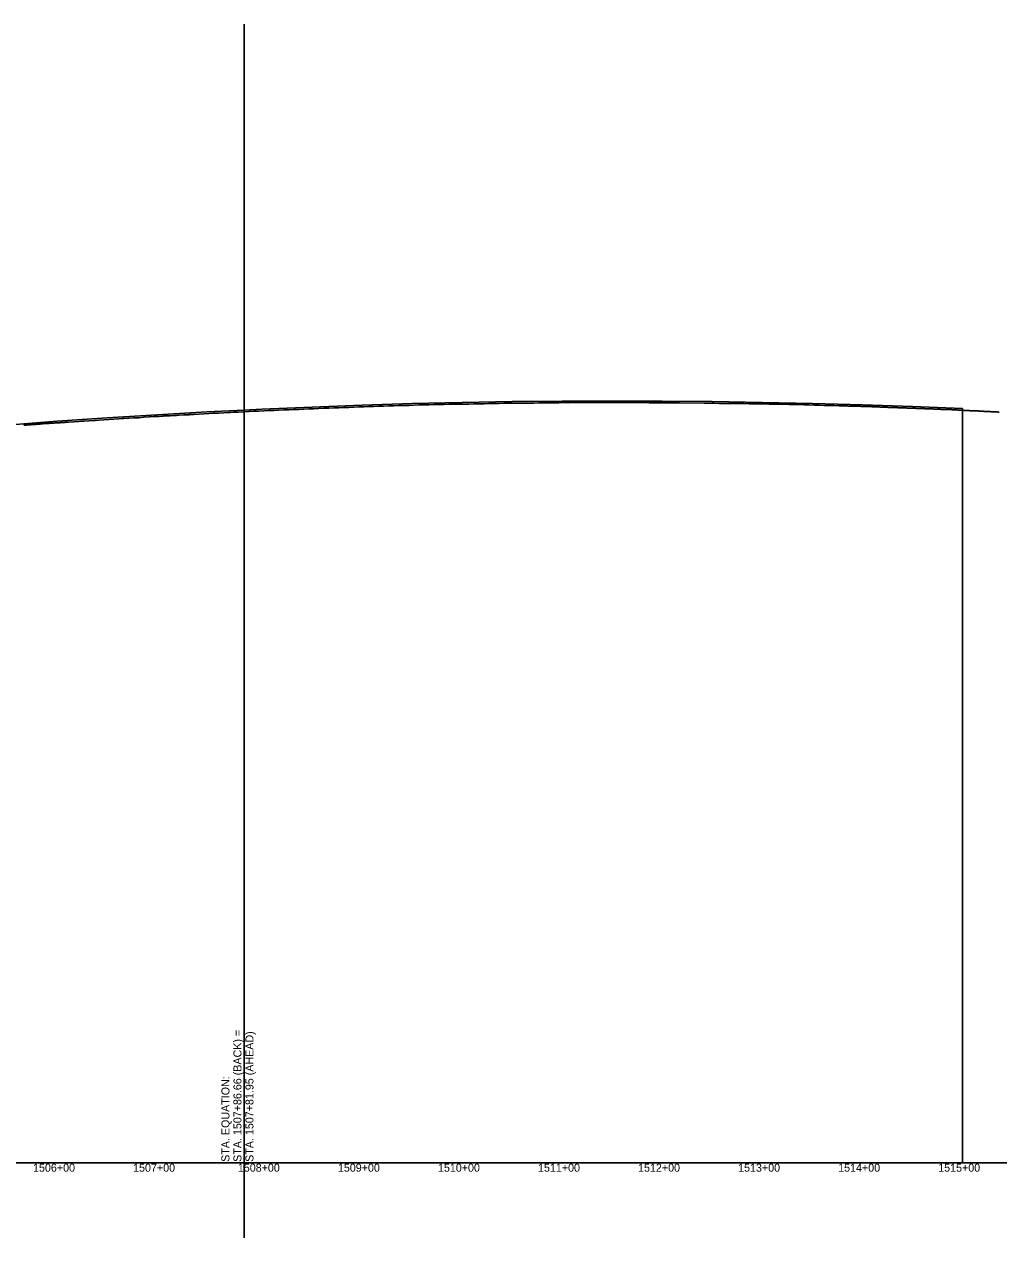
# Model space of a CAD drawing. Extents: x -3793 to 50787, y -1075 to 6138.
# Drawn here: x 38006 to 38979, y -1075 to 138 of the extents above; entities that cross this region are included whole.
import ezdxf

# ---------------------------------------------------------------- set-up
doc = ezdxf.new("R2010")
doc.units = 0
for name, color, linetype in [('RD_DDB_Profile_EX', 7, 'Continuous'), ('RD_DDB_Profile_PR', 7, 'Continuous'), ('RD_DDB_StaTX', 7, 'Continuous'), ('RD_GPK_Profile_Cell', 7, 'Continuous'), ('RD_Sketch10', 7, 'Continuous')]:
    doc.layers.add(name, color=color, linetype=linetype)

msp = doc.modelspace()

# ---------------------------------------------------------------- linework, layer by layer
at = {"layer": 'RD_DDB_Profile_EX'}
for points in [[(38225.12583, -249.34735), (38229.923127, -249.107085), (38234.921278, -248.85725), (38239.91943, -248.60742), (38244.914277, -248.307705), (38249.921926, -248.107355), (38254.916721, -247.95605), (38259.914874, -247.656985), (38264.919173, -247.45596), (38269.914027, -247.255755), (38274.91218, -247.105605), (38279.916482, -246.904965), (38284.914634, -246.60574), (38289.909419, -246.50461), (38294.904246, -246.304085), (38299.911928, -246.054385), (38304.906705, -245.85404), (38309.90486, -245.65423), (38314.909207, -245.45351), (38319.907362, -245.303505), (38324.905517, -245.153685), (38329.907033, -244.905105), (38334.90522, -244.70477), (38339.906728, -244.456305), (38344.914373, -244.306045), (38349.915949, -244.157005), (38354.914076, -244.00681), (38359.915634, -243.75899), (38364.913756, -243.65919), (38369.911877, -243.558495), (38374.912871, -243.407015), (38379.907641, -243.156765), (38384.911987, -243.056315), (38389.906757, -242.9554), (38394.901526, -242.75478), (38399.902501, -242.55338), (38404.897278, -242.452735), (38409.901607, -242.30204), (38414.896376, -242.201235), (38419.900723, -242.10048), (38423.783513, -242.022265), (38424.895965, -242.0001), (38429.892311, -241.85117), (38434.899805, -241.801125), (38439.89729, -241.75091), (38444.894194, -241.65144), (38449.901704, -241.651395), (38454.899173, -241.50134), (38459.896101, -241.401715), (38464.893566, -241.25168), (38469.901076, -241.151635), (38474.898544, -241.101375), (38479.895454, -240.95184), (38484.892924, -240.85181), (38489.899879, -240.802255), (38494.896791, -240.752715), (38499.903704, -240.753275), (38504.900612, -240.654), (38509.89752, -240.70419), (38514.904408, -240.654745), (38519.901386, -240.5552), (38524.908257, -240.505755), (38529.905163, -240.4071), (38534.902069, -240.35714), (38539.908914, -240.307215), (38544.905362, -240.20886), (38549.912187, -240.259445), (38554.90977, -240.208685), (38559.906657, -240.208505), (38564.914179, -240.20653), (38589.48124, -240.20871), (38590.094524, -240.20887), (38614.922181, -240.22192), (38619.925883, -240.17011), (38624.930332, -240.22002), (38629.928395, -240.32082), (38634.790286, -240.354835), (38635.484839, -240.35691), (38659.827095, -240.528185), (38660.275519, -240.529525), (38684.9043, -240.704345), (38689.901765, -240.754615), (38694.899231, -240.85412), (38699.897327, -240.903845), (38704.894792, -240.953725), (38709.902239, -240.953995), (38714.900324, -241.10304), (38719.89779, -241.102915), (38724.895818, -241.20226), (38729.893286, -241.252135), (38734.891337, -241.301605), (38739.888804, -241.45124), (38744.896853, -241.550725), (38749.894322, -241.650605), (38755.190084, -241.658935), (38759.890462, -241.800175), (38761.390288, -241.815015), (38764.886732, -241.85028), (38769.893123, -241.95129), (38774.88948, -242.00239), (38779.896393, -242.103135)], [(38779.896393, -242.103135), (38784.892742, -242.303595), (38789.899063, -242.454585), (38794.895973, -242.605385), (38799.902257, -242.75695), (38804.898709, -242.906855), (38809.905545, -243.057315), (38814.901891, -243.10957), (38820.037785, -243.260785), (38821.028694, -243.3097), (38822.023276, -243.359295), (38823.027495, -243.408275), (38824.020655, -243.45771), (38825.024876, -243.45811), (38826.019448, -243.55773), (38827.023804, -243.55743), (38828.026599, -243.557645), (38829.021183, -243.60726), (38830.025522, -243.60755), (38831.01998, -243.65713), (38832.022901, -243.65793), (38833.027258, -243.65758), (38834.021701, -243.70663), (38835.026059, -243.75582), (38836.019081, -243.756445), (38837.023439, -243.75612), (38838.027783, -243.805355), (38839.022243, -243.85497), (38840.025163, -243.855185), (38841.019691, -243.855205), (38842.023971, -243.954125), (38843.017069, -243.95463), (38844.021351, -244.00433), (38845.0257, -244.0537), (38846.020222, -244.05365), (38847.023081, -244.103865), (38848.0176, -244.05406), (38849.021947, -244.053975), (38850.026255, -244.15312), (38851.019326, -244.20351), (38852.023681, -244.20316), (38853.018132, -244.25271), (38854.022488, -244.30253), (38855.025373, -244.252985), (38856.019867, -244.252625), (38857.024219, -244.302325), (38858.018678, -244.40165), (38859.021599, -244.501725), (38860.016073, -244.55124), (38861.020412, -244.600865), (38862.024769, -244.60052), (38863.017792, -244.650695), (38864.022149, -244.750255), (38864.584437, -244.77827), (38865.016858, -244.80024), (38866.021663, -244.850665), (38867.024259, -244.85038), (38868.019297, -244.85096), (38869.024098, -244.951335), (38870.01693, -244.95115), (38871.01953, -244.95089), (38872.024335, -245.0512), (38873.017163, -245.051145), (38874.019765, -245.100735), (38875.022359, -245.10047), (38876.017399, -245.15102), (38877.02, -245.200715), (38878.022593, -245.20043), (38879.015426, -245.250225), (38880.020232, -245.300615), (38881.022828, -245.300345), (38882.015659, -245.300185), (38883.02046, -245.350685), (38884.023061, -245.400325), (38885.015892, -245.450105), (38885.321238, -245.45), (38886.018714, -245.4502), (38886.520224, -245.499935), (38887.023295, -245.55024), (38888.110474, -245.604705), (38889.019016, -245.65023), (38890.021931, -245.650515), (38891.016394, -245.650035), (38892.019317, -245.70032), (38893.022233, -245.75057), (38894.015264, -245.800685), (38895.019619, -245.850335), (38896.022533, -245.850585), (38897.015565, -245.90079), (38898.01849, -245.95106), (38899.022834, -246.00064), (38900.015866, -246.05079), (38901.018789, -246.05119), (38902.023134, -246.00089), (38903.016168, -246.101025), (38904.01909, -246.101255), (38905.021994, -246.151445), (38906.016469, -246.25096), (38907.019392, -246.301315), (38908.022295, -246.3516), (38909.015338, -246.401665)], [(38004.928264, -262.77775), (38005.921257, -262.67944), (38006.923787, -262.62909), (38007.925908, -262.528735), (38009.021716, -262.473645), (38009.921443, -262.42598), (38010.923611, -262.32371), (38011.926177, -262.227345), (38012.919165, -262.128865), (38013.921347, -262.126625), (38014.923914, -262.07443), (38015.916887, -262.022205), (38016.919084, -261.92376), (38017.92165, -261.871665), (38018.924216, -261.72496), (38019.91717, -261.674555), (38020.919387, -261.57424), (38021.921953, -261.523925), (38022.528223, -261.462595), (38022.914905, -261.426895), (38023.917201, -261.37489), (38024.919799, -261.226235), (38025.912755, -261.1742), (38026.915031, -261.1239), (38027.917628, -261.073605), (38028.920226, -261.02331), (38029.913165, -260.971385), (38030.915458, -260.87261), (38031.919047, -260.821675), (38032.911965, -260.72128), (38033.91428, -260.66958), (38034.916878, -260.61655), (38036.03473, -260.55374), (38036.912139, -260.46869), (38037.914768, -260.41845), (38038.917398, -260.36821), (38039.910065, -260.26787), (38040.912695, -260.265115), (38041.915324, -260.16615), (38042.908234, -260.06706), (38043.910621, -259.968015), (38044.91325, -259.966575), (38045.906149, -259.9174), (38046.90857, -259.81827), (38047.9112, -259.767995), (38048.913829, -259.716615), (38049.541237, -259.65456), (38049.938228, -259.616465), (38054.940515, -259.363235), (38059.933174, -259.01305), (38063.047745, -258.825575), (38064.935608, -258.71115), (38069.928388, -258.310185), (38074.931195, -258.010045), (38076.554252, -257.912185), (38079.92417, -257.70849), (38084.927287, -257.40779), (38090.060759, -257.04911), (38094.92377, -256.755485), (38099.91715, -256.40541), (38103.567266, -256.14973), (38104.920563, -256.054975), (38109.914331, -255.804945), (38114.917979, -255.503885), (38117.073773, -255.395995), (38119.911357, -255.2537), (38124.915313, -254.854625), (38129.90987, -254.55379), (38130.58028, -254.506805), (38134.914731, -254.20319), (38139.910158, -253.901805), (38144.086787, -253.60822), (38144.905638, -253.55075), (38149.900816, -253.40021), (38151.179983, -253.32334), (38154.910201, -253.10094), (38157.593294, -252.967555), (38159.911002, -252.851975), (38164.908162, -252.552505), (38169.908677, -252.253605), (38171.099801, -252.182515), (38174.918326, -251.95443), (38179.91831, -251.605325), (38184.914965, -251.305515), (38189.914408, -251.05583), (38194.923375, -250.806365), (38198.112816, -250.678685), (38199.91929, -250.605505), (38204.918278, -250.25674), (38209.926709, -250.05841), (38211.619323, -249.97362), (38214.921946, -249.80718)], [(38214.921946, -249.80718), (38219.920358, -249.60745), (38225.12583, -249.34735)], [(38909.015338, -246.401665), (38910.019693, -246.45129), (38911.022595, -246.45166), (38912.015639, -246.50172), (38913.018562, -246.502125), (38914.022896, -246.551615), (38915.015941, -246.60178), (38916.018836, -246.602185), (38917.021756, -246.702315), (38918.016238, -246.751715), (38919.020574, -246.751555), (38920.023493, -246.75196), (38921.01797, -246.85125), (38922.020872, -246.951415), (38923.015349, -246.950965), (38924.018271, -247.001215), (38925.022613, -247.000865), (38926.017082, -247.050415), (38927.020004, -247.050715), (38928.014462, -247.050245), (38929.017383, -247.1005), (38930.02174, -247.150125), (38931.014763, -247.150325), (38932.019226, -247.20012), (38933.02403, -247.25062), (38934.016863, -247.25042), (38935.021663, -247.35086), (38936.014499, -247.400655), (38937.019305, -247.45119), (38938.021896, -247.50083), (38939.01694, -247.60147), (38940.019537, -247.75106), (38941.014575, -247.70184), (38942.019378, -247.75236), (38943.021976, -247.801895), (38944.017012, -247.80266), (38945.019611, -247.952285), (38946.014667, -248.052685), (38947.017245, -248.10223), (38948.022045, -248.10282), (38949.017072, -248.15343), (38950.019679, -248.202935), (38951.014742, -248.30333), (38952.017306, -248.303355), (38953.02211, -248.303835), (38954.014974, -248.403625), (38955.019734, -248.4541), (38956.014812, -248.45471), (38957.01741, -248.50437), (38958.02216, -248.50484), (38959.015045, -248.55464), (38960.017642, -248.654295), (38961.022393, -248.70477), (38962.015278, -248.754565), (38963.017875, -248.804225), (38964.022627, -248.854695), (38965.01551, -248.95427), (38966.018108, -249.003945), (38967.02286, -249.054395), (38968.015743, -249.05442), (38969.01834, -249.103875), (38970.023094, -249.154325), (38971.015976, -249.20435), (38972.020773, -249.25458), (38973.013601, -249.304155), (38974.016208, -249.30428), (38975.020959, -249.35475), (38976.013834, -249.40477), (38977.016441, -249.404205), (38978.021193, -249.45468), (38979.014066, -249.60425), (38980.016674, -249.654135)]]:
    msp.add_lwpolyline(points, dxfattribs=at)
at = {"layer": 'RD_DDB_Profile_PR'}
for points in [[(38225.13, -247.708067), (38243.18, -246.812), (38293.18, -244.7735), (38343.18, -242.758), (38393.18, -241.224), (38443.18, -240.0855), (38493.18, -239.17), (38543.18, -238.643), (38593.18, -238.6105), (38643.18, -238.811), (38693.18, -239.22), (38743.18, -239.9165), (38793.18, -240.9535), (38843.18, -242.3625), (38893.18, -244.1585), (38943.18, -246.202)], [(37038.47, -347.3695), (37088.47, -342.7665), (37138.47, -338.378), (37188.47, -334.063), (37238.47, -329.6575), (37288.47, -325.2545), (37338.47, -320.543), (37388.47, -315.9615), (37438.47, -311.554), (37488.47, -307.091), (37538.47, -302.9095), (37588.47, -298.354), (37638.47, -293.692), (37688.47, -289.4125), (37738.47, -284.969), (37788.47, -280.5125), (37838.47, -275.8645), (37888.47, -271.361), (37938.47, -267.136), (37988.47, -262.6795), (38038.47, -258.7905), (38088.47, -255.5605), (38138.47, -252.389)], [(38138.47, -252.389), (38188.47, -249.528), (38225.13, -247.708067)]]:
    msp.add_lwpolyline(points, dxfattribs=at)
at = {"layer": 'RD_GPK_Profile_Cell'}
msp.add_line((1000, -1000), (46610.921919, -1000), dxfattribs=at)
at = {"layer": 'RD_Sketch10'}
for p, q in [((38225.13, -1000), (38225.13, 138.027692)), ((38943.18, -1000), (38943.18, -246.202)), ((38225.13, -1000), (38225.13, -1075))]:
    msp.add_line(p, q, dxfattribs=at)

# ---------------------------------------------------------------- texts
at = {"layer": 'RD_DDB_StaTX'}
for s, p in [('1506+00', (38014.263622, -1009)), ('1506+00', (38014.265471, -1009)), ('1507+00', (38114.263622, -1009)), ('1507+00', (38114.265471, -1009)), ('1508+00', (38218.971301, -1009)), ('1508+00', (38218.975471, -1009)), ('1509+00', (38318.971301, -1009)), ('1509+00', (38318.975471, -1009)), ('1510+00', (38418.971301, -1009)), ('1510+00', (38418.975471, -1009)), ('1511+00', (38518.971301, -1009)), ('1511+00', (38518.975471, -1009)), ('1512+00', (38618.971301, -1009)), ('1512+00', (38618.975471, -1009)), ('1513+00', (38718.971301, -1009)), ('1513+00', (38718.975471, -1009)), ('1514+00', (38818.971301, -1009)), ('1514+00', (38818.975471, -1009)), ('1515+00', (38918.971301, -1009)), ('1515+00', (38918.975471, -1009))]:
    msp.add_text(s, height=8, dxfattribs=at).set_placement(p)
at = {"layer": 'RD_Sketch10'}
for s, p in [('STA. 1507+86.66 (BACK) =', (38222.56195, -999.159336)), ('STA. 1507+81.95 (AHEAD)', (38234.56195, -999.159336)), ('STA. EQUATION:', (38210.56195, -999.159336))]:
    msp.add_text(s, height=8, rotation=90, dxfattribs=at).set_placement(p)

doc.saveas('drawing.dxf')
